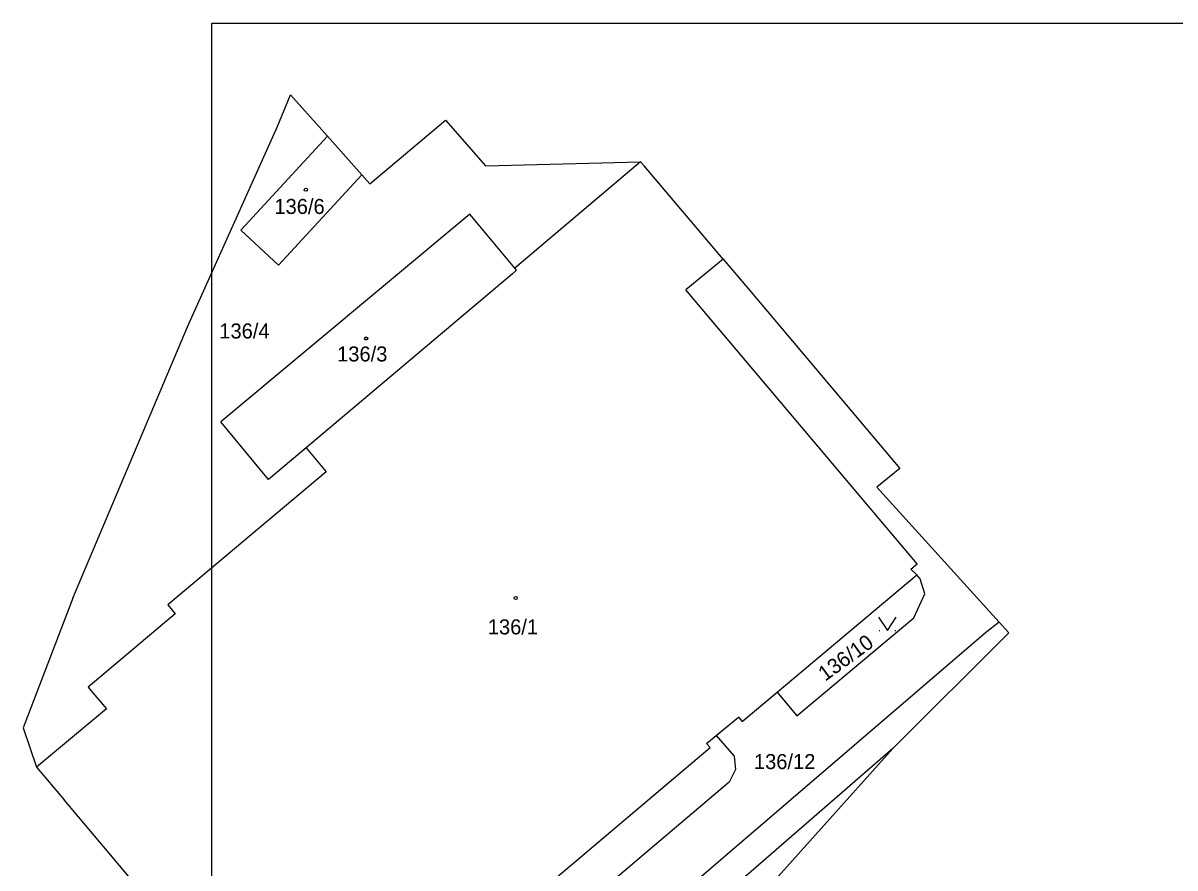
# Model space of a CAD drawing. Extents: x -670359 to -660124, y -978807 to -970072.
# Drawn here: x -670021.4 to -669891.1, y -977095.5 to -977000 of the extents above; entities that cross this region are included whole.
import ezdxf

# ---------------------------------------------------------------- set-up
doc = ezdxf.new("R2010")
doc.units = 0
for name, color, linetype in [('Hranice kat_území', 7, 'Continuous'), ('Hranice parcel', 7, 'Continuous'), ('ML1000', 7, 'Continuous'), ('Parcelní čísla', 7, 'Continuous'), ('Značky budov', 7, 'Continuous'), ('Značky kultur', 7, 'Continuous')]:
    doc.layers.add(name, color=color, linetype=linetype)

msp = doc.modelspace()

# ---------------------------------------------------------------- linework, layer by layer
at = {"layer": 'Hranice kat_území'}
for points in [[(-669992.62, -977011.79), (-669991.11, -977008.11)], [(-669991.11, -977008.11), (-669986.94, -977012.79)], [(-669982.16, -977018.18), (-669973.59, -977011)], [(-669973.59, -977011), (-669969.06, -977016.14)], [(-670002.78, -977034.35), (-669992.62, -977011.79)], [(-669986.94, -977012.79), (-669983.07, -977017.16)], [(-669969.06, -977016.14), (-669951.54, -977015.68)], [(-669951.54, -977015.68), (-669951.12, -977016.16)], [(-669942.2, -977026.71), (-669951.12, -977016.16)], [(-669983.07, -977017.16), (-669982.16, -977018.18)], [(-669942.2, -977026.71), (-669939.42, -977029.99)], [(-669939.42, -977029.99), (-669922.23, -977050.36)], [(-670015.73, -977065.05), (-670002.78, -977034.35)], [(-669922.23, -977050.36), (-669924.83, -977052.47)], [(-669924.83, -977052.47), (-669910.99, -977067.73)], [(-670015.73, -977065.05), (-670021.36, -977079.69)], [(-669910.99, -977067.73), (-669909.88, -977068.95)], [(-669909.88, -977068.95), (-669923, -977082.05)], [(-670021.36, -977079.69), (-670019.82, -977084.16)], [(-669923, -977082.05), (-669935.98, -977096.52)], [(-670019.82, -977084.16), (-670016.71, -977087.84)], [(-670008.23, -977097.9), (-670016.71, -977087.84)]]:
    msp.add_lwpolyline(points, dxfattribs=at)
at = {"layer": 'Hranice parcel'}
for points in [[(-669996.75, -977023.43), (-669986.94, -977012.79)], [(-669951.54, -977015.68), (-669965.74, -977027.72)], [(-669992.49, -977027.36), (-669983.07, -977017.16)], [(-669965.74, -977027.72), (-669970.83, -977021.62), (-669999.01, -977045.11)], [(-669996.75, -977023.43), (-669992.49, -977027.36)], [(-669942.2, -977026.71), (-669946.42, -977030.15)], [(-669966, -977028.37), (-669965.55, -977027.95), (-669965.74, -977027.72)], [(-669966, -977028.37), (-669989.36, -977048.04)], [(-669920.25, -977061.14), (-669946.42, -977030.15)], [(-669993.62, -977051.63), (-669999.01, -977045.11)], [(-669989.36, -977048.04), (-669993.62, -977051.63)], [(-669989.36, -977048.04), (-669987.1, -977050.73)], [(-669987.1, -977050.73), (-670005, -977065.78), (-670004.16, -977066.8), (-670013.98, -977075.09), (-670013.48, -977075.72)], [(-669920.31, -977062.39), (-669920.97, -977061.75), (-669920.25, -977061.14)], [(-669936.1, -977075.65), (-669920.31, -977062.39)], [(-669919.91, -977062.86), (-669920.31, -977062.39)], [(-669919.38, -977064.56), (-669919.91, -977062.86)], [(-669920.65, -977067.27), (-669919.38, -977064.56)], [(-669933.87, -977078.32), (-669920.65, -977067.27)], [(-669910.99, -977067.73), (-669912.53, -977068.97)], [(-669912.53, -977068.97), (-669971.42, -977119.44)], [(-670013.48, -977075.72), (-670011.93, -977077.54)], [(-669942.99, -977080.58), (-669940.46, -977078.5), (-669940.06, -977078.98), (-669936.1, -977075.65)], [(-669936.1, -977075.65), (-669933.87, -977078.32)], [(-670011.93, -977077.54), (-670019.82, -977084.16)], [(-669962.47, -977097.83), (-669943.67, -977081.93), (-669944.07, -977081.47), (-669942.99, -977080.58)], [(-669942.99, -977080.58), (-669940.95, -977082.9)], [(-669923, -977082.05), (-669967.72, -977120.86)], [(-669940.95, -977082.9), (-669940.8, -977084.4)], [(-669940.8, -977084.4), (-669941.51, -977085.83)], [(-669941.51, -977085.83), (-669973.04, -977112.58)]]:
    msp.add_lwpolyline(points, dxfattribs=at)
at = {"layer": 'ML1000'}
msp.add_lwpolyline([(-669375, -977000), (-669375, -977500), (-670000, -977500), (-670000, -977000)], close=True, dxfattribs=at)
at = {"layer": 'Značky budov'}
for centre in [(-669989.38, -977018.85), (-669982.56, -977035.67), (-669965.65, -977065.01)]:
    msp.add_circle(centre, 0.175, dxfattribs=at)
at = {"layer": 'Značky kultur'}
for p, q in [((-669924.57, -977068.67), (-669924.47, -977068.67)), ((-669922.77, -977068.67), (-669922.67, -977068.67))]:
    msp.add_line(p, q, dxfattribs=at)
msp.add_lwpolyline([(-669924.62, -977067.17), (-669923.62, -977068.67), (-669922.62, -977067.17)], dxfattribs=at)
for centre in [(-669989.38, -977018.85), (-669982.56, -977035.67), (-669965.65, -977065.01)]:
    msp.add_circle(centre, 0.175, dxfattribs=at)

# ---------------------------------------------------------------- texts
at = {"layer": 'Parcelní čísla'}
for s, p in [('136/6', (-669992.94, -977021.59)), ('136/4', (-669999.17, -977035.67)), ('136/3', (-669985.85, -977038.27)), ('136/1', (-669968.81, -977069.13)), ('136/12', (-669938.72, -977084.36))]:
    msp.add_text(s, height=1.7, dxfattribs=at).set_placement(p)
msp.add_text('136/10', height=1.7, rotation=36.0274, dxfattribs=at).set_placement((-669930.66, -977074.49))

doc.saveas('drawing.dxf')
